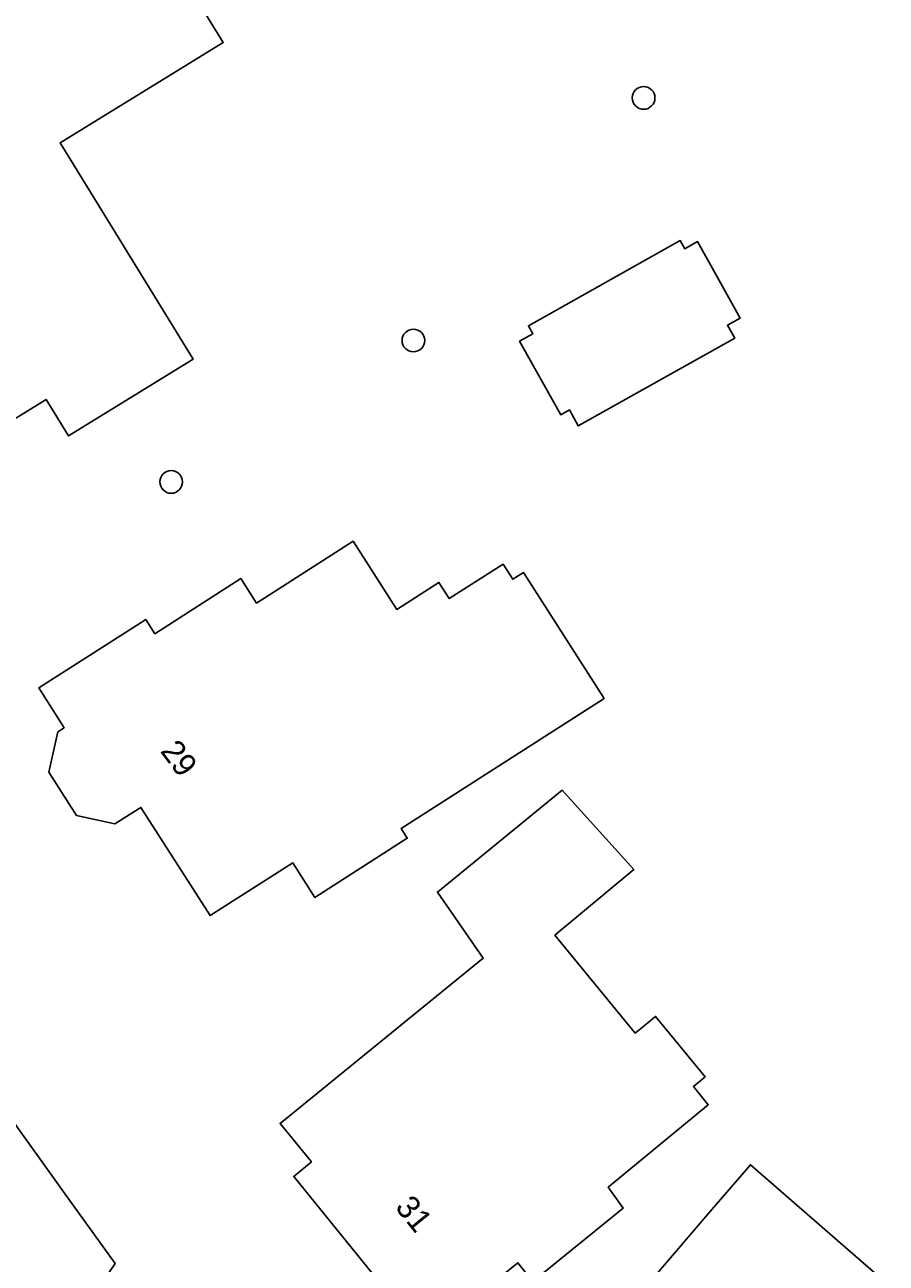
# Model space of a CAD drawing. Extents: x 161347 to 161881, y 382161 to 382804.
# Drawn here: x 161671.5 to 161708.6, y 382336.2 to 382389.6 of the extents above; entities that cross this region are included whole.
import ezdxf

# ---------------------------------------------------------------- set-up
doc = ezdxf.new("R2010")
doc.units = 0
for name, color, linetype in [('IMGEO_Boom', 7, 'Continuous'), ('IMGEO_Erf', 7, 'Continuous'), ('IMGEO_Pand', 7, 'Continuous'), ('IMGEO_Pand_nummerreeks', 7, 'Continuous'), ('IMGEO_Voetpad_open', 7, 'Continuous')]:
    doc.layers.add(name, color=color, linetype=linetype)

msp = doc.modelspace()

# ---------------------------------------------------------------- linework, layer by layer
at = {"layer": 'IMGEO_Boom'}
for centre in [(161698.181, 382386.422), (161688.251, 382375.969), (161677.807, 382369.873)]:
    msp.add_circle(centre, 0.489, dxfattribs=at)
at = {"layer": 'IMGEO_Erf'}
for points in [[(161596.873, 382461.934), (161606.595, 382446.199), (161610.46, 382439.943), (161617.351, 382428.79), (161618.821, 382426.407), (161625.713, 382415.253), (161627.403, 382412.518), (161635.49, 382399.431), (161637.176, 382396.702), (161644.13, 382385.439), (161645.645, 382382.995), (161648.386, 382378.558), (161650.079, 382375.819), (161660.585, 382358.814), (161662.853, 382355.14), (161668.204, 382346.482), (161670.894, 382342.449), (161673.167, 382339.282), (161675.39, 382336.184)], [(161697.644, 382334.447), (161701.127, 382338.509), (161702.784, 382340.442), (161708.643, 382335.359)]]:
    msp.add_lwpolyline(points, dxfattribs=at)
for points in [[(161677.771, 382392.171), (161677.925, 382392.266), (161680.052, 382388.813), (161673.016, 382384.481), (161678.753, 382375.162), (161673.383, 382371.854), (161672.415, 382373.427), (161667.493, 382370.396), (161660.166, 382382.295), (161669.286, 382387.911), (161665.916, 382393.386), (161671.721, 382396.96), (161673.97, 382398.345), (161676.539, 382394.172)], [(161702.346, 382376.936), (161701.795, 382376.626), (161702.108, 382376.068), (161695.364, 382372.286), (161694.978, 382372.974), (161694.61, 382372.767), (161692.832, 382375.938), (161693.404, 382376.259), (161693.21, 382376.603), (161699.757, 382380.273), (161699.956, 382379.919), (161700.5, 382380.229)], [(161696.484, 382360.535), (161687.724, 382354.929), (161687.988, 382354.516), (161684.004, 382351.967), (161683.051, 382353.458), (161679.491, 382351.181), (161676.502, 382355.846), (161675.382, 382355.13), (161673.728, 382355.494), (161672.537, 382357.356), (161672.92, 382359.101), (161673.193, 382359.276), (161672.094, 382360.994), (161676.307, 382363.689), (161676.711, 382363.947), (161677.104, 382363.332), (161680.81, 382365.704), (161681.483, 382364.651), (161685.652, 382367.318), (161687.532, 382364.375), (161689.355, 382365.54), (161689.802, 382364.841), (161692.122, 382366.324), (161692.537, 382365.676), (161693.005, 382365.975)], [(161697.755, 382353.161), (161694.352, 382350.333), (161697.822, 382346.113), (161698.203, 382346.426), (161698.7, 382346.834), (161700.84, 382344.233), (161700.325, 382343.81), (161700.969, 382343.026), (161696.655, 382339.476), (161697.292, 382338.567), (161693.41, 382335.415), (161692.759, 382336.218), (161688.753, 382332.965), (161683.091, 382339.943), (161683.854, 382340.562), (161682.503, 382342.228), (161691.267, 382349.342), (161689.288, 382352.192), (161694.67, 382356.587)]]:
    msp.add_lwpolyline(points, close=True, dxfattribs=at)
at = {"layer": 'IMGEO_Pand'}
for points in [[(161676.539, 382394.172), (161673.97, 382398.345), (161671.721, 382396.96), (161665.916, 382393.386), (161669.286, 382387.911), (161660.166, 382382.295), (161667.493, 382370.396), (161672.415, 382373.427), (161673.383, 382371.854), (161678.753, 382375.162), (161673.016, 382384.481), (161680.052, 382388.813), (161677.925, 382392.266), (161677.771, 382392.171)], [(161693.21, 382376.603), (161693.404, 382376.259), (161692.832, 382375.938), (161694.61, 382372.767), (161694.978, 382372.974), (161695.364, 382372.286), (161702.108, 382376.068), (161701.795, 382376.626), (161702.346, 382376.936), (161700.5, 382380.229), (161699.956, 382379.919), (161699.757, 382380.273)], [(161696.484, 382360.535), (161693.005, 382365.975), (161692.537, 382365.676), (161692.122, 382366.324), (161689.802, 382364.841), (161689.355, 382365.54), (161687.532, 382364.375), (161685.652, 382367.318), (161681.483, 382364.651), (161680.81, 382365.704), (161677.104, 382363.332), (161676.711, 382363.947), (161676.307, 382363.689), (161672.094, 382360.994), (161673.193, 382359.276), (161672.92, 382359.101), (161672.537, 382357.356), (161673.728, 382355.494), (161675.382, 382355.13), (161676.502, 382355.846), (161679.491, 382351.181), (161683.051, 382353.458), (161684.004, 382351.967), (161687.988, 382354.516), (161687.724, 382354.929)], [(161689.288, 382352.192), (161691.267, 382349.342), (161682.503, 382342.228), (161683.854, 382340.562), (161683.091, 382339.943), (161688.753, 382332.965), (161692.759, 382336.218), (161693.41, 382335.415), (161697.292, 382338.567), (161696.655, 382339.476), (161700.969, 382343.026), (161700.325, 382343.81), (161700.84, 382344.233), (161698.7, 382346.834), (161698.203, 382346.426), (161697.822, 382346.113), (161694.352, 382350.333), (161697.755, 382353.161), (161694.67, 382356.587)], [(161707.794, 382333.736), (161707.512, 382333.942), (161708.643, 382335.359), (161702.784, 382340.442), (161701.127, 382338.509), (161697.644, 382334.447), (161700.071, 382332.684), (161697.426, 382329.042), (161696.924, 382329.406), (161693.197, 382324.274), (161695.317, 382322.735), (161695.49, 382321.644), (161697.801, 382319.966), (161706.639, 382332.144)]]:
    msp.add_lwpolyline(points, close=True, dxfattribs=at)
at = {"layer": 'IMGEO_Voetpad_open'}
msp.add_lwpolyline([(161670.894, 382342.449), (161666.872, 382341.08), (161670.126, 382336.516), (161672.905, 382332.54), (161675.39, 382336.184), (161673.167, 382339.282)], close=True, dxfattribs=at)

# ---------------------------------------------------------------- texts
at = {"layer": 'IMGEO_Pand_nummerreeks'}
for s, rotation, p in [('29', 307.0088, (161677.307, 382358.264)), ('31', 309.0583, (161687.429, 382338.596))]:
    msp.add_text(s, height=1, rotation=rotation, dxfattribs=at).set_placement(p)

doc.saveas('drawing.dxf')
